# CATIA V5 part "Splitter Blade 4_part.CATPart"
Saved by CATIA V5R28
Part number: Splitter Blade 4_part
Definition: design
Nomenclature: Splitter Blade 4_part
Source: Unknown
Bounding box of the stored display mesh (mm): x -0.263 to 8.631, y 3.62 to 5.936, z 4.237 to 7.742
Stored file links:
  D:\paraturbo-cad\STEP\Turbocompressor_for_Christophe\Splitter Blade 4_part.CATPart
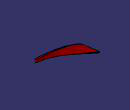
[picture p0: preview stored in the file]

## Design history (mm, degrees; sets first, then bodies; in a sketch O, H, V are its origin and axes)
Body1 "MANIFOLD_SOLID_BREP #66798" (main body)
  Solid1: solid without history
